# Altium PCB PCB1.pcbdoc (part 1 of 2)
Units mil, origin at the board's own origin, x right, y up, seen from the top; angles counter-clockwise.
Board outline 3200 x 1800 mil, 2 copper layers (Top Layer, Bottom Layer), stack 62.206 mil thick; 104 components, 97 nets, 542 pads, 186 vias.
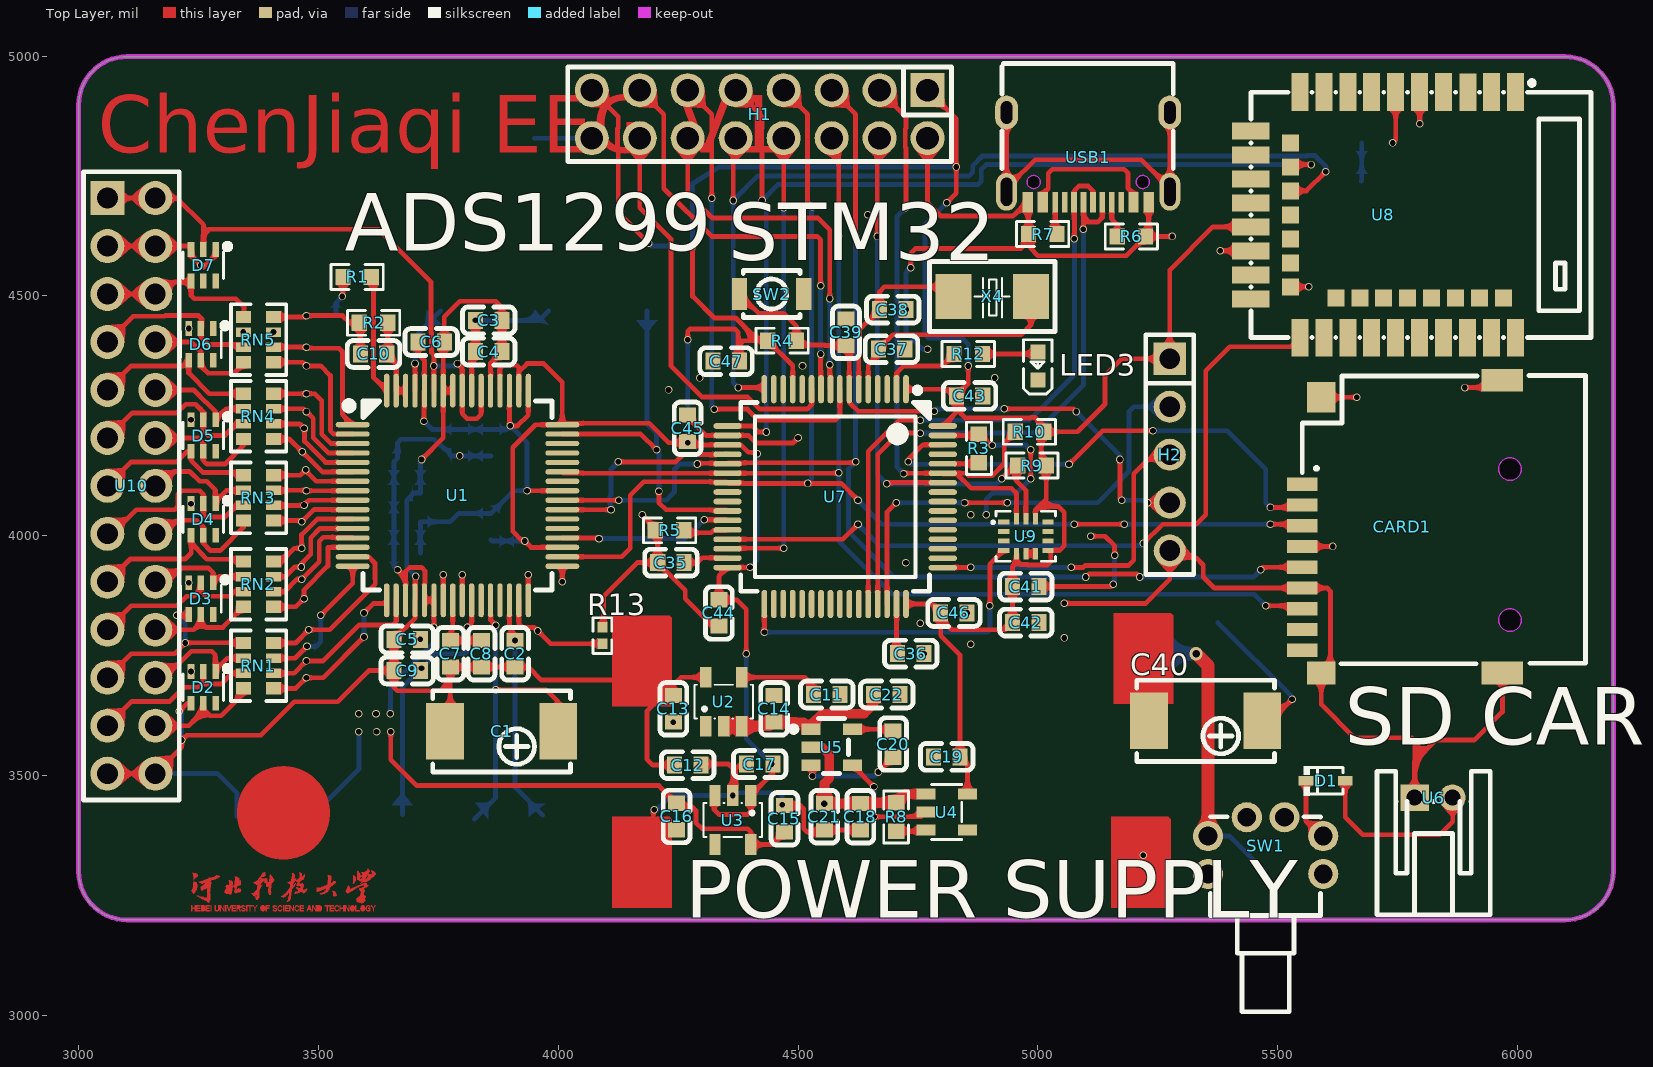
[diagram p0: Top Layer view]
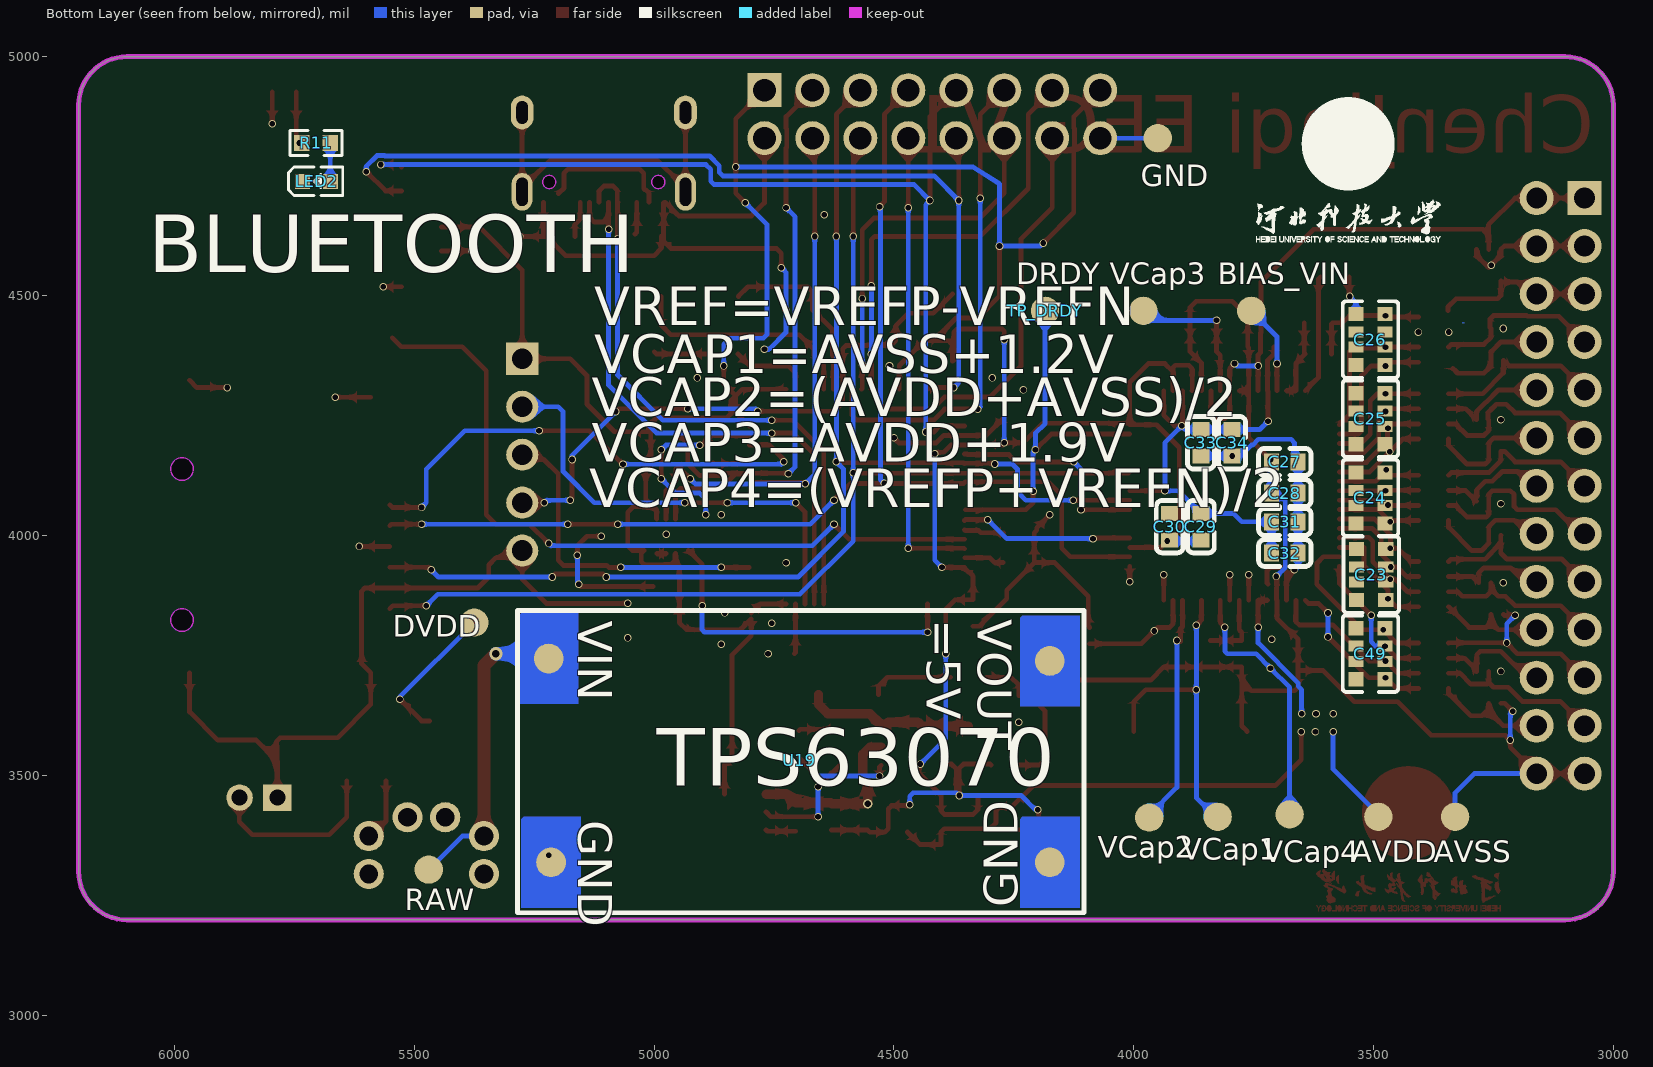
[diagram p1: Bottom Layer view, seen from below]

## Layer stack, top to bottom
Top Solder Mask Layer: solder mask 0.394, Dk 3.3
Top Layer: signal copper 1.379
Dielectric1: surface 59.449, FR4, Dk 4.5
Bottom Layer: signal copper 1.378
Bottom Solder Mask Layer: solder mask 0.394, Dk 3.3

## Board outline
3101.06,4998.82 ccw(c3101.06,4897.75) 3000,4897.75 3000,3299.88 ccw(c3101.06,3299.88) 3101.06,3198.82 6098.94,3198.82 ccw(c6098.94,3299.88) 6200,3299.88 6200,4897.75 ccw(c6098.94,4897.75) 6098.94,4998.82

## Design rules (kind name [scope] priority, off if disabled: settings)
BoardOutlineClearance copperThickness1oz [All] p0: genericclearance=10 ignorepadtopadclearanceinfootprint=FALSE except(0: Arc-SplitContinuation Track-SplitContinuation SMDPad-SplitContinuation THPad-SplitContinuation Via-SplitContinuation Fill-SplitContinuation Poly-SplitContinuation Region-SplitContinuation Text-SplitContinuation)
BoardOutlineClearance copperThickness2oz [All] p0: genericclearance=10 ignorepadtopadclearanceinfootprint=FALSE except(0: Arc-SplitContinuation Track-SplitContinuation SMDPad-SplitContinuation THPad-SplitContinuation Via-SplitContinuation Fill-SplitContinuation Poly-SplitContinuation Region-SplitContinuation Text-SplitContinuation)
BoardOutlineClearance otherClearance [All] p0: genericclearance=10 ignorepadtopadclearanceinfootprint=FALSE except(0: Arc-SplitContinuation Track-SplitContinuation SMDPad-SplitContinuation THPad-SplitContinuation Via-SplitContinuation Fill-SplitContinuation Poly-SplitContinuation Region-SplitContinuation Text-SplitContinuation)
Clearance copperThickness1oz [All] p1: gap=7 ignorepadtopadclearanceinfootprint=FALSE
Clearance copperThickness2oz [All] p1: gap=7 ignorepadtopadclearanceinfootprint=FALSE
Clearance otherClearance [All] p1: gap=7 ignorepadtopadclearanceinfootprint=FALSE
DiffPairsRouting differentialPair [All] p1: maxuncoupledlength=10 minlimit=6 maxlimit=Infinity mostfreqgap=6 toplayer_minwidth=5 toplayer_prefwidth=10 toplayer_maxwidth=100 bottomlayer_minwidth=5 bottomlayer_prefwidth=10 bottomlayer_maxwidth=100
PasteMaskExpansion pasteMaskExpansion [All] p1: expansion=0
PlaneConnect innerPlane [All] p1: planeconnectstyle=Relief reliefexpansion=20 reliefentries=4 reliefconductorwidth=10 reliefairgap=10
PolygonConnect copperRegion [All] p1: connectstyle=Relief reliefentries=4 reliefconductorwidth=10 polygonreliefangle="90 Angle" airgapwidth=10
PolygonConnect copperRegion1 [All] p1: connectstyle=Direct reliefentries=4 reliefconductorwidth=10 polygonreliefangle="90 Angle" airgapwidth=10
RoutingVias viaSize [All] p1: viastyle="Through Hole" holewidth=11.811 minholewidth=7.874 maxholewidth=27.559 width=11.811 minwidth=7.874 maxwidth=27.559
RoutingVias viaSize1 [All] p1: viastyle="Through Hole" holewidth=11.811 minholewidth=11.811 maxholewidth=11.811 width=11.811 minwidth=11.811 maxwidth=11.811
RoutingVias viaSize2 [All] p1: viastyle="Through Hole" holewidth=12.0078 minholewidth=11.811 maxholewidth=248.0314 width=12.0078 minwidth=11.811 maxwidth=248.0314
RoutingVias viaSize3 [All] p1: viastyle="Through Hole" holewidth=15.748 minholewidth=11.811 maxholewidth=248.0314 width=15.748 minwidth=11.811 maxwidth=248.0314
SolderMaskExpansion solderMaskExpansion [IsVia] p1: useseparateexpansions=TRUE expansion=-1000 expansionbottom=-1000
SolderMaskExpansion solderMaskExpansion [All] p2: useseparateexpansions=TRUE expansion=2 expansionbottom=2
Width copperThickness1oz [All] p1: maxlimit=100 minlimit=5 preferedwidth=10
Width copperThickness2oz [All] p1: maxlimit=100 minlimit=8 preferedwidth=10

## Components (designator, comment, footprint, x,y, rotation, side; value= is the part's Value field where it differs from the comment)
AVDD "" Test-Point-0.5mm 3490,3413.82 r180 bottom
AVSS "" Test-Point-0.5mm 3330,3413.82 r180 bottom
BIAS_VIN "" Test-Point-0.5mm 3755,4468.82 r180 bottom
C1 "100uF" CAP-SMD_L7.3-W4.3-RD_177EC0013 3881.89,3591.93 r0 top
C2 "100nF" C0603 3910,3753.82 r90 top
C3 "100nF" C0603 3855,4448.82 r0 top
C4 "100nF" C0603 3855,4383.82 r0 top
C5 "100nF" C0603 3685,3783.82 r180 top
C6 "100nF" C0603 3735,4403.82 r180 top
C7 "100nF" C0603 3775,3753.82 r90 top
C8 "100nF" C0603 3840,3753.82 r90 top
C9 "100nF" C0603 3685,3718.82 r0 top
C10 "100nF" C0603 3615,4378.82 r180 top
C11 "100nF" C0603 4560,3668.82 r180 top
C12 "100nF" C0603 4270.01,3521.68 r180 top
C13 "100nF" C0603 4240,3638.82 r270 top
C14 "100nF" C0603 4450,3638.82 r270 top
C15 "100nF" C0603 4471.76,3409.61 r270 top
C16 "100nF" C0603 4246.76,3414.49 r90 top
C17 "100nF" C0603 4420,3523.82 r0 top
C18 "100nF" C0603 4630,3413.82 r90 top
C19 "100nF" C0603 4810,3538.82 r0 top
C20 "100nF" C0603 4698.3,3565.47 r90 top
C21 "100nF" C0603 4555,3413.82 r90 top
C22 "100nF" C0603 4684.88,3668.82 r180 top
C23 "100nF" CAP-ARRAY-SMD_6124-8P-L1.6-W3.2-BL 3505,3918.82 r90 bottom
C24 "100nF" CAP-ARRAY-SMD_6124-8P-L1.6-W3.2-BL 3506.47,4078.82 r90 bottom
C25 "100nF" CAP-ARRAY-SMD_6124-8P-L1.6-W3.2-BL 3506.47,4243.82 r90 bottom
C26 "100nF" CAP-ARRAY-SMD_6124-8P-L1.6-W3.2-BL 3506.47,4408.82 r90 bottom
C27 "100nF" C0603 3685,4153.82 r180 bottom
C28 "100nF" C0603 3685,4088.82 r180 bottom
C29 "100nF" C0603 3860,4018.82 r270 bottom
C30 "100nF" C0603 3925,4018.82 r270 bottom
C31 "100nF" C0603 3685,4028.82 r180 bottom
C32 "100nF" C0603 3685,3963.82 r180 bottom
C33 "100nF" C0603 3860,4193.82 r270 bottom
C34 "100nF" C0603 3795,4193.82 r270 bottom
C35 "100nF" C0603 4235,3943.82 r180 top
C36 "100nF" C0603 4735,3753.82 r0 top
C37 "100nF" C0603 4695,4388.82 r0 top
C38 "100nF" C0603 4697.66,4471.4 r0 top
C39 "100nF" C0603 4600,4423.82 r90 top
C40 "100uF" CAP-SMD_L7.3-W4.3-RD_177EC0013 5350,3613.82 r0 top
C41 "100nF" C0603 4975,3893.82 r180 top
C42 "100nF" C0603 4975,3818.82 r180 top
C43 "100nF" C0603 4857.56,4291.38 r0 top
C44 "100nF" C0603 4335,3838.82 r270 top
C45 "100nF" C0603 4270,4223.82 r90 top
C46 "100nF" C0603 4825,3838.82 r0 top
C47 "100nF" C0603 4350,4363.82 r0 top
C49 "100nF" CAP-ARRAY-SMD_6124-8P-L1.6-W3.2-BL 3506.47,3753.82 r90 bottom
CARD1 "TF PUSH" TF-SMD_TF-PUSH 5760,4018.82 r90 top
D1 "B5819WS" SOD-323_L1.7-W1.3-LS2.5-FD 5600,3488.82 r180 top
D2 "TPD4E1B06DCKR" SC-70-6_L2.2-W1.3-P0.65-LS2.1-BL 3260,3683.82 r180 top
D3 "TPD4E1B06DCKR" SC-70-6_L2.2-W1.3-P0.65-LS2.1-BL 3255,3868.82 r180 top
D4 "TPD4E1B06DCKR" SC-70-6_L2.2-W1.3-P0.65-LS2.1-BL 3260,4033.82 r180 top
D5 "TPD4E1B06DCKR" SC-70-6_L2.2-W1.3-P0.65-LS2.1-BL 3260,4208.82 r180 top
D6 "TPD4E1B06DCKR" SC-70-6_L2.2-W1.3-P0.65-LS2.1-BL 3255,4398.82 r180 top
D7 "TPD4E1B06DCKR" SC-70-6_L2.2-W1.3-P0.65-LS2.1-BL 3260,4563.82 r180 top
DVDD "" Test-Point-0.5mm 5375,3818.82 r180 bottom
GND "" Test-Point-0.5mm 3950,4828.82 r180 bottom
H1 "PZ254V-12-16P" HDR-TH_16P-P2.54-V-M-R2-C8-S2.54 4420,4878.82 r180 top
H2 "PZ254V-11-05P" HDR-TH_5P-P2.54-V-M 5275,4168.82 r270 top
LED2 "LTST-C190KSKT" LED0603-RD 5703.98,4738.81 r180 bottom
LED3 "LTST-C190KSKT" LED0603-RD 5000,4353.82 r90 top
R1 "10K" R0603 3580.68,4539.5 r180 top
R2 "10K" R0603 3615,4443.82 r180 top
R3 "10K" R0603 4877.08,4181.86 r90 top
R4 "10K" R0603 4466.74,4406.52 r180 top
R5 "10K" R0603 4232.08,4011.18 r180 top
R6 "10K" R0603 5195,4623.82 r180 top
R7 "10K" R0603 5010,4628.82 r0 top
R8 "10K" R0603 4704.66,3413.48 r270 top
R9 "10K" R0603 4987.76,4146.18 r0 top
R10 "10K" R0603 4982.42,4216.52 r0 top
R11 "10K" R0603 5705,4818.82 r180 bottom
R12 "10K" R0603 4855,4378.82 r0 top
R13 "0Ω" R0402 4092.04,3791.78 r90 top
RAW "" Test-Point-0.5mm 5470,3303.82 r180 bottom
RN1 "2kΩ" RES-ARRAY-SMD_0603-8P-L3.2-W1.6-BL 3375,3728.82 r270 top
RN2 "2kΩ" RES-ARRAY-SMD_0603-8P-L3.2-W1.6-BL 3375,3898.82 r270 top
RN3 "2kΩ" RES-ARRAY-SMD_0603-8P-L3.2-W1.6-BL 3375,4078.82 r270 top
RN4 "2kΩ" RES-ARRAY-SMD_0603-8P-L3.2-W1.6-BL 3375,4248.82 r270 top
RN5 "2kΩ" RES-ARRAY-SMD_0603-8P-L3.2-W1.6-BL 3375,4408.82 r270 top
SW1 "XKB5858-Z-E" SW-TH_XKB5858-Z-E 5475,3353.82 r180 top
SW2 "B3U-1000P" KEY-SMD_B3U-1000PM 4445,4503.82 r0 top
TP_DRDY "" Test-Point-0.5mm 4185,4468.82 r90 bottom
U1 "ADS1299IPAGR" TQFP-64_L10.0-W10.0-P0.50-LS12.0-TL 3790,4083.82 r0 top
U2 "TPS72325DBVR" SOT-23-5_L3.0-W1.7-P0.95-LS2.8-BR 4345,3653.82 r270 top
U3 "TLV70025DDCR" SOT-23-5_L3.0-W1.7-P0.95-LS2.8-BR 4364.2,3407.05 r90 top
U4 "MCP1754T-3302E/OT" SOT-23-5_L2.9-W1.6-P0.95-LS2.9-BL 4810,3423.82 r270 top
U5 "TPS60401QDBVRQ1" SOT-23-5_L2.9-W1.6-P0.95-LS2.8-BR 4570,3558.82 r180 top
U6 "S2B-PH-K-S(LF)(SN)" CONN-TH_S2B-PH-K-S-LF-SN 5825,3453.82 r180 top
U7 "STM32F405RGT6" LQFP-64_L10.0-W10.0-P0.50-LS12.0-BL 4577.42,4081.52 r180 top
U8 "E73-2G4M08S1C" WIRELM-SMD_E73-2G4M08S1C 5720,4668.82 r90 top
U9 "BMI270" LGA-14_L3.0-W2.5-P0.50-BR 4975,3998.82 r180 top
U10 "DS1021-2x13SF11-B" HDR-TH_26P-P2.54-V-M-R2-C13-S2.54 3110,4103.82 r270 top
U19 "" tps63070模块 4765,3548.82 r180 bottom
USB1 "TYPE-C 16PIN 2MD(073)" USB-C-SMD_TYPE-C-16PIN-2MD-073 5105,4788.82 r180 top
VCap1 "" Test-Point-0.5mm 3825,3413.82 r90 bottom
VCap2 "" Test-Point-0.5mm 3967.72,3412.26 r90 bottom
VCap3 "" Test-Point-0.5mm 3980,4468.82 r180 bottom
VCap4 "" Test-Point-0.5mm 3675,3418.82 r90 bottom
X4 "8MHz" CRYSTAL-SMD_L5.0-W3.2 4905,4498.82 r0 top

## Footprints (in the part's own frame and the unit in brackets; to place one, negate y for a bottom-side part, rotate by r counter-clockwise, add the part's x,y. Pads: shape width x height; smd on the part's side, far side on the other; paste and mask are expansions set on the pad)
C0603 [mm]
  rect 0.8x0.9 smd: 1(-0.7,0) 2(0.7,0)
  silkscreen extent -1.39,-0.71 1.39,0.71
CAP-ARRAY-SMD_6124-8P-L1.6-W3.2-BL [mm]
  rect 0.75x0.8 smd: 1(-1.35,-0.77) 4(1.35,-0.77) 5(1.35,0.77) 8(-1.35,0.77)
  rect 0.58x0.8 smd: 2(-0.4,-0.77) 3(0.4,-0.77) 6(0.4,0.77) 7(-0.4,0.77)
  silkscreen extent -2.02,-1.47 2.02,1.47
CAP-SMD_L7.3-W4.3-RD_177EC0013 [mm]
  rect 2x3 smd paste+0 mask+0.05: 1(-3,0) 2(3,0)
  silkscreen extent -3.65,-2.15 3.65,2.15
CONN-TH_S2B-PH-K-S-LF-SN [mm]
  rect 1.5x1.4 hole 0.85: 1(1,0)
  round 1.4 hole 0.85: 2(-1,0)
  silkscreen extent -3,-1.4 3,6.2
CRYSTAL-SMD_L5.0-W3.2 [mm]
  rect 1.9x2.4 smd: 1(-2.05,0) 2(2.05,0)
  silkscreen extent -3.32,-1.85 3.33,1.85
HDR-TH_5P-P2.54-V-M [mm]
  rect 1.7x1.7 hole 1.1: 1(-5.08,0)
  round 1.7 hole 1.1: 2(-2.54,0) 3(0,0) 4(2.54,0) 5(5.08,0)
  silkscreen extent -6.35,-1.27 6.35,1.27
HDR-TH_16P-P2.54-V-M-R2-C8-S2.54 [mm]
  rect 1.8x1.8 hole 1.2: 1(-8.89,-1.27)
  round 1.8 hole 1.2: 2(-8.89,1.27) 3(-6.35,-1.27) 4(-6.35,1.27) 5(-3.81,-1.27) 6(-3.81,1.27) 7(-1.27,-1.27) 8(-1.27,1.27) 9(1.27,-1.27) 10(1.27,1.27) 11(3.81,-1.27) 12(3.81,1.27) 13(6.35,-1.27) 14(6.35,1.27) 15(8.89,-1.27) 16(8.89,1.27)
  silkscreen extent -10.16,-2.5 10.16,2.5
HDR-TH_26P-P2.54-V-M-R2-C13-S2.54 [mm]
  rect 1.8x1.8 hole 1.1: 1(-15.24,-1.27)
  round 1.8 hole 1.1: 2(-15.24,1.27) 3(-12.7,-1.27) 4(-12.7,1.27) 5(-10.16,-1.27) 6(-10.16,1.27) 7(-7.62,-1.27) 8(-7.62,1.27) 9(-5.08,-1.27) 10(-5.08,1.27) 11(-2.54,-1.27) 12(-2.54,1.27) 13(0,-1.27) 14(0,1.27) 15(2.54,-1.27) 16(2.54,1.27) 17(5.08,-1.27) 18(5.08,1.27) 19(7.62,-1.27) 20(7.62,1.27) 21(10.16,-1.27) 22(10.16,1.27) 23(12.7,-1.27) 24(12.7,1.27) 25(15.24,-1.27) 26(15.24,1.27)
  silkscreen extent -16.64,-2.54 16.64,2.54
KEY-SMD_B3U-1000PM [mm]
  rect 0.8x1.7 smd: 1(-1.7,0) 2(1.7,0)
  silkscreen extent -1.5,-1.25 1.5,1.25
LED0603-RD [mm]
  rect 0.8x0.8 smd: 1(-0.749,0) 2(0.749,0)
  silkscreen extent -1.49,-0.75 1.39,0.76
LGA-14_L3.0-W2.5-P0.50-BR [mm]
  rect 0.6x0.27 smd: 1(1.17,-0.75) 2(1.17,-0.25) 3(1.17,0.25) 4(1.17,0.75) 8(-1.17,0.75) 9(-1.17,0.25) 10(-1.17,-0.25) 11(-1.17,-0.75)
  rect 0.27x0.6 smd: 5(0.5,0.92) 6(0,0.92) 7(-0.5,0.92) 12(-0.5,-0.92) 13(0,-0.92) 14(0.5,-0.92)
  silkscreen extent -1.58,-1.33 1.8,1.33
LQFP-64_L10.0-W10.0-P0.50-LS12.0-BL [mm]
  oval 0.3x1.5 smd: 1(-3.75,-5.688) 2(-3.25,-5.688) 3(-2.75,-5.688) 4(-2.25,-5.688) 5(-1.75,-5.688) 6(-1.25,-5.688) 7(-0.75,-5.688) 8(-0.25,-5.688) 9(0.25,-5.688) 10(0.75,-5.688) 11(1.25,-5.688) 12(1.75,-5.688) 13(2.25,-5.688) 14(2.75,-5.688) 15(3.25,-5.688) 16(3.75,-5.688) 33(3.75,5.688) 34(3.25,5.688) 35(2.75,5.688) 36(2.25,5.688) 37(1.75,5.688) 38(1.25,5.688) 39(0.75,5.688) 40(0.25,5.688) 41(-0.25,5.688) 42(-0.75,5.688) 43(-1.25,5.688) 44(-1.75,5.688) 45(-2.25,5.688) 46(-2.75,5.688) 47(-3.25,5.688) 48(-3.75,5.688)
  oval 1.5x0.3 smd: 17(5.7,-3.738) 18(5.7,-3.238) 19(5.7,-2.738) 20(5.7,-2.238) 21(5.7,-1.738) 22(5.7,-1.238) 23(5.7,-0.738) 24(5.7,-0.238) 25(5.7,0.262) 26(5.7,0.762) 27(5.7,1.262) 28(5.7,1.762) 29(5.7,2.262) 30(5.7,2.762) 31(5.7,3.262) 32(5.7,3.762) 49(-5.7,3.762) 50(-5.7,3.262) 51(-5.7,2.762) 52(-5.7,2.262) 53(-5.7,1.762) 54(-5.7,1.262) 55(-5.7,0.762) 56(-5.7,0.262) 57(-5.7,-0.238) 58(-5.7,-0.738) 59(-5.7,-1.238) 60(-5.7,-1.738) 61(-5.7,-2.238) 62(-5.7,-2.738) 63(-5.7,-3.238) 64(-5.7,-3.738)
  silkscreen extent -5,-5.78 5,5.01
R0402 [mm]
  rect 0.566x0.54 smd paste-100 mask+0.051: 1(-0.433,0) 2(0.433,0)
  silkscreen extent -0.94,-0.5 0.94,0.5
R0603 [mil]
  rect 31.75x34.02 smd paste-3937.01 mask+2: 1(-29.66,0) 2(29.66,0)
  silkscreen extent -55,-26 55,26
RES-ARRAY-SMD_0603-8P-L3.2-W1.6-BL [mm]
  rect 0.65x0.8 smd: 1(-1.2,-0.8) 4(1.2,-0.8) 5(1.2,0.8) 8(-1.2,0.8)
  rect 0.5x0.8 smd: 2(-0.4,-0.8) 3(0.4,-0.8) 6(0.4,0.8) 7(-0.4,0.8)
  silkscreen extent -1.87,-1.45 1.87,1.47
SC-70-6_L2.2-W1.3-P0.65-LS2.1-BL [mm]
  rect 0.35x0.78 smd: 1(-0.65,-0.84) 2(0,-0.84) 3(0.65,-0.84) 4(0.65,0.84) 5(0,0.84) 6(-0.65,0.84)
  silkscreen extent -1.43,-1.14 1.08,0.7
SOD-323_L1.7-W1.3-LS2.5-FD [mm]
  rect 0.78x0.5 smd: 1(-1.04,0) 2(1.04,0)
  silkscreen extent -0.93,-0.78 1.15,0.78
SOT-23-5_L2.9-W1.6-P0.95-LS2.8-BR [mm]
  rect 1x0.6 smd paste+0 mask+0.05: 1(1.1,-0.95) 2(1.1,0) 3(1.1,0.95) 4(-1.1,0.95) 5(-1.1,-0.95)
  silkscreen extent -0.89,-1.52 2.16,1.4
SOT-23-5_L2.9-W1.6-P0.95-LS2.9-BL [mm]
  rect 0.6x1 smd paste+0 mask+0.05: 1(-0.95,-1.1) 2(0,-1.1) 3(0.95,-1.1) 4(0.95,1.1) 5(-0.95,1.1)
  silkscreen extent -1.45,-0.8 1.45,0.8
SOT-23-5_L3.0-W1.7-P0.95-LS2.8-BR [mm]
  rect 1.1x0.6 smd: 1(1.3,-0.95) 2(1.3,0) 3(1.3,0.95) 4(-1.3,0.95) 5(-1.3,-0.95)
  silkscreen extent -0.9,-1.55 0.9,1.55
SW-TH_XKB5858-Z-E [mm]
  round 1.6 hole 1: 1(-3.05,1.5) 2(-3.05,-0.5) 3(3.05,1.5) 4(3.05,-0.5) 5(-1,-1.5) 6(1,-1.5)
  silkscreen extent -2.9,-1.52 2.92,8.8
Test-Point-0.5mm [mm]
  round 1.5 smd: 1(0,0)
TF-SMD_TF-PUSH [mm]
  rect 0.7x1.6 smd: 1(2.25,5.3) 2(1.15,5.3) 3(0.05,5.3) 4(-1.05,5.3) 5(-2.15,5.3) 6(-3.25,5.3) 7(-4.35,5.3) 8(-5.45,5.3) CD(-6.55,5.3)
  rect 1.2x1.5 smd: 10(-7.75,4.3)
  rect 1.2x2.2 smd: 11(-7.75,-5.3) 12(7.75,-5.3)
  rect 1.6x1.5 smd: 13(6.85,4.3)
  Board Outline Layer circle w0.003: c-4.95,-5.7 r0.6
  Board Outline Layer circle w0.003: c3.05,-5.7 r0.6
  Board Outline Layer region: -4.95,-6.3 -5.21,-6.241 -5.419,-6.074 -5.535,-5.834 -5.535,-5.567 -5.419,-5.326 -5.21,-5.159 -4.95,-5.1 -4.95,-5.1 -4.69,-5.159 -4.481,-5.326 -4.365,-5.567 -4.365,-5.834 -4.481,-6.074 -4.69,-6.241 -4.95,-6.3
  Board Outline Layer region: -4.95,-6.3 -5.054,-6.291 -5.155,-6.264 -5.25,-6.22 -5.336,-6.16 -5.41,-6.086 -5.47,-6 -5.514,-5.905 -5.541,-5.804 -5.55,-5.7 -5.541,-5.596 -5.514,-5.495 -5.47,-5.4 -5.41,-5.314 -5.336,-5.24 -5.25,-5.18 -5.155,-5.136 -5.054,-5.109 -4.95,-5.1 -4.846,-5.109 -4.745,-5.136 -4.65,-5.18 -4.564,-5.24 -4.49,-5.314 -4.43,-5.4 -4.386,-5.495 -4.359,-5.596 -4.35,-5.7 -4.359,-5.804 -4.386,-5.905 -4.43,-6 -4.49,-6.086 -4.564,-6.16 -4.65,-6.22 -4.745,-6.264 -4.846,-6.291
  Board Outline Layer region: 3.05,-6.3 2.79,-6.241 2.581,-6.074 2.465,-5.834 2.465,-5.567 2.581,-5.326 2.79,-5.159 3.05,-5.1 3.05,-5.1 3.31,-5.159 3.519,-5.326 3.635,-5.567 3.635,-5.834 3.519,-6.074 3.31,-6.241 3.05,-6.3
  Board Outline Layer region: 3.05,-6.3 2.946,-6.291 2.845,-6.264 2.75,-6.22 2.664,-6.16 2.59,-6.086 2.53,-6 2.486,-5.905 2.459,-5.804 2.45,-5.7 2.459,-5.596 2.486,-5.495 2.53,-5.4 2.59,-5.314 2.664,-5.24 2.75,-5.18 2.845,-5.136 2.946,-5.109 3.05,-5.1 3.154,-5.109 3.255,-5.136 3.35,-5.18 3.436,-5.24 3.51,-5.314 3.57,-5.4 3.614,-5.495 3.641,-5.596 3.65,-5.7 3.641,-5.804 3.614,-5.905 3.57,-6 3.51,-6.086 3.436,-6.16 3.35,-6.22 3.255,-6.264 3.154,-6.291
  Multi-Layer board cut-out: -4.95,-6.3 -5.21,-6.241 -5.419,-6.074 -5.535,-5.834 -5.535,-5.567 -5.419,-5.326 -5.21,-5.159 -4.95,-5.1 -4.95,-5.1 -4.69,-5.159 -4.481,-5.326 -4.365,-5.567 -4.365,-5.834 -4.481,-6.074 -4.69,-6.241 -4.95,-6.3
  Multi-Layer board cut-out: 3.05,-6.3 2.79,-6.241 2.581,-6.074 2.465,-5.834 2.465,-5.567 2.581,-5.326 2.79,-5.159 3.05,-5.1 3.05,-5.1 3.31,-5.159 3.519,-5.326 3.635,-5.567 3.635,-5.834 3.519,-6.074 3.31,-6.241 3.05,-6.3
  silkscreen extent -7.26,-9.7 8,5.3
tps63070模块 [mm]
  round 1.571 smd: 1(-11.556,4.952) 2(-11.429,-5.843) 3(14.987,4.825) 4(14.987,-5.843)
  Top Layer region: -13.015,7.357 -9.985,7.357 -9.985,2.549 -13.129,2.549 -13.129,7.243
  Top Layer region: -12.888,-3.438 -9.858,-3.438 -9.858,-8.246 -13.002,-8.246 -13.002,-3.552
  Top Layer region: 13.528,7.23 16.558,7.23 16.558,2.422 13.414,2.422 13.414,7.116
  Top Layer region: 13.528,-3.438 16.558,-3.438 16.558,-8.246 13.414,-8.246 13.414,-3.552
  Bottom Layer region: -13.015,7.357 -9.985,7.357 -9.985,2.549 -13.129,2.549 -13.129,7.243
  Bottom Layer region: -12.888,-3.438 -9.858,-3.438 -9.858,-8.246 -13.002,-8.246 -13.002,-3.552
  Bottom Layer region: 13.528,7.23 16.558,7.23 16.558,2.422 13.414,2.422 13.414,7.116
  Bottom Layer region: 13.528,-3.438 16.558,-3.438 16.558,-8.246 13.414,-8.246 13.414,-3.552
  Multi-Layer region: -13.015,7.357 -9.985,7.357 -9.985,2.549 -13.129,2.549 -13.129,7.243
  Multi-Layer region: -12.888,-3.438 -9.858,-3.438 -9.858,-8.246 -13.002,-8.246 -13.002,-3.552
  Multi-Layer region: 13.528,7.23 16.558,7.23 16.558,2.422 13.414,2.422 13.414,7.116
  Multi-Layer region: 13.528,-3.438 16.558,-3.438 16.558,-8.246 13.414,-8.246 13.414,-3.552
  silkscreen extent -13.21,-8.51 16.79,7.49
TQFP-64_L10.0-W10.0-P0.50-LS12.0-TL [mm]
  oval 1.8x0.28 smd paste-100 mask+0.051: 1(-5.55,3.75) 2(-5.55,3.25) 3(-5.55,2.75) 4(-5.55,2.25) 5(-5.55,1.75) 6(-5.55,1.25) 7(-5.55,0.75) 8(-5.55,0.25) 9(-5.55,-0.25) 10(-5.55,-0.75) 11(-5.55,-1.25) 12(-5.55,-1.75) 13(-5.55,-2.25) 14(-5.55,-2.75) 15(-5.55,-3.25) 16(-5.55,-3.75) 33(5.55,-3.75) 34(5.55,-3.25) 35(5.55,-2.75) 36(5.55,-2.25) 37(5.55,-1.75) 38(5.55,-1.25) 39(5.55,-0.75) 40(5.55,-0.25) 41(5.55,0.25) 42(5.55,0.75) 43(5.55,1.25) 44(5.55,1.75) 45(5.55,2.25) 46(5.55,2.75) 47(5.55,3.25) 48(5.55,3.75)
  oval 0.28x1.8 smd paste-100 mask+0.051: 17(-3.75,-5.55) 18(-3.25,-5.55) 19(-2.75,-5.55) 20(-2.25,-5.55) 21(-1.75,-5.55) 22(-1.25,-5.55) 23(-0.75,-5.55) 24(-0.25,-5.55) 25(0.25,-5.55) 26(0.75,-5.55) 27(1.25,-5.55) 28(1.75,-5.55) 29(2.25,-5.55) 30(2.75,-5.55) 31(3.25,-5.55) 32(3.75,-5.55) 49(3.75,5.55) 50(3.25,5.55) 51(2.75,5.55) 52(2.25,5.55) 53(1.75,5.55) 54(1.25,5.55) 55(0.75,5.55) 56(0.25,5.55) 57(-0.25,5.55) 58(-0.75,5.55) 59(-1.25,5.55) 60(-1.75,5.55) 61(-2.25,5.55) 62(-2.75,5.55) 63(-3.25,5.55) 64(-3.75,5.55)
  silkscreen extent -5.95,-5 5,5
USB-C-SMD_TYPE-C-16PIN-2MD-073 [mm]
  oval 1.2x1.8 hole 0.6 slot 1.2 at 90 deg paste+0 mask+0.05: 13(-4.325,-2.375) 14(4.325,-2.375)
  oval 1.1x2 hole 0.6 slot 1.5 at 90 deg paste+0 mask+0.05: 13(-4.325,1.825) 14(4.325,1.825)
  rect 0.55x1.1 smd paste+0 mask+0.05: A1B12(-3.2,2.375) A4B9(-2.4,2.375) B1A12(3.2,2.375) B4A9(2.4,2.375)
  rect 0.3x1.1 smd paste+0 mask+0.05: A5(-1.25,2.375) A6(-0.25,2.375) A7(0.25,2.375) A8(1.25,2.375) B5(1.75,2.375) B6(0.75,2.375) B7(-0.75,2.375) B8(-1.75,2.375)
  Board Outline Layer circle w0.003: c-2.89,1.305 r0.35
  Board Outline Layer circle w0.003: c2.89,1.305 r0.35
  Board Outline Layer region: -3.24,1.305 -3.205,1.457 -3.108,1.579 -2.968,1.646 -2.812,1.646 -2.672,1.579 -2.575,1.457 -2.54,1.305 -2.54,1.305 -2.575,1.153 -2.672,1.031 -2.812,0.964 -2.968,0.964 -3.108,1.031 -3.205,1.153 -3.24,1.305
  Board Outline Layer region: -3.24,1.305 -3.231,1.383 -3.205,1.457 -3.164,1.523 -3.108,1.579 -3.042,1.62 -2.968,1.646 -2.89,1.655 -2.812,1.646 -2.738,1.62 -2.672,1.579 -2.616,1.523 -2.575,1.457 -2.549,1.383 -2.54,1.305 -2.549,1.227 -2.575,1.153 -2.616,1.087 -2.672,1.031 -2.738,0.99 -2.812,0.964 -2.89,0.955 -2.968,0.964 -3.042,0.99 -3.108,1.031 -3.164,1.087 -3.205,1.153 -3.231,1.227
  Board Outline Layer region: 2.54,1.305 2.575,1.457 2.672,1.579 2.812,1.646 2.968,1.646 3.108,1.579 3.205,1.457 3.24,1.305 3.24,1.305 3.205,1.153 3.108,1.031 2.968,0.964 2.812,0.964 2.672,1.031 2.575,1.153 2.54,1.305
  Board Outline Layer region: 2.54,1.305 2.549,1.383 2.575,1.457 2.616,1.523 2.672,1.579 2.738,1.62 2.812,1.646 2.89,1.655 2.968,1.646 3.042,1.62 3.108,1.579 3.164,1.523 3.205,1.457 3.231,1.383 3.24,1.305 3.231,1.227 3.205,1.153 3.164,1.087 3.108,1.031 3.042,0.99 2.968,0.964 2.89,0.955 2.812,0.964 2.738,0.99 2.672,1.031 2.616,1.087 2.575,1.153 2.549,1.227
  Multi-Layer board cut-out: -3.24,1.305 -3.205,1.457 -3.108,1.579 -2.968,1.646 -2.812,1.646 -2.672,1.579 -2.575,1.457 -2.54,1.305 -2.54,1.305 -2.575,1.153 -2.672,1.031 -2.812,0.964 -2.968,0.964 -3.108,1.031 -3.205,1.153 -3.24,1.305
  Multi-Layer board cut-out: 2.54,1.305 2.575,1.457 2.672,1.579 2.812,1.646 2.968,1.646 3.108,1.579 3.205,1.457 3.24,1.305 3.24,1.305 3.205,1.153 3.108,1.031 2.968,0.964 2.812,0.964 2.672,1.031 2.575,1.153 2.54,1.305
  silkscreen extent -4.5,-4.97 4.57,0.6
WIRELM-SMD_E73-2G4M08S1C [mm]
  rect 2x0.9 smd paste+0 mask+0.05: 1(6.505,-7.015) 2(6.505,-5.745) 3(6.5,-4.5) 4(6.505,-3.205) 5(6.505,-1.935) 6(6.505,-0.665) 7(6.505,0.605) 8(6.505,1.875) 9(6.505,3.145) 10(6.505,4.415) 26(-6.505,4.415) 27(-6.505,3.145) 29(-6.505,1.875) 31(-6.505,0.605) 33(-6.505,-0.665) 35(-6.505,-1.935) 37(-6.505,-3.205) 39(-6.505,-4.475) 41(-6.505,-5.745) 43(-6.505,-7.015)
  rect 0.9x2 smd paste+0 mask+0.05: 11(4.445,7.015) 13(3.175,7.015) 15(1.905,7.015) 17(0.635,7.015) 19(-0.635,7.015) 21(-1.905,7.015) 23(-3.175,7.015) 25(-4.445,7.015)
  rect 0.9x0.9 smd paste+0 mask+0.05: 12(3.81,4.915) 14(2.54,4.915) 16(1.27,4.915) 18(0,4.915) 20(-1.27,4.915) 22(-2.54,4.915) 24(-3.81,4.915) 28(-4.405,2.51) 30(-4.405,1.24) 32(-4.405,-0.03) 34(-4.405,-1.3) 36(-4.405,-2.57) 38(-4.405,-3.84) 40(-4.405,-5.11) 42(-4.405,-6.38)
  silkscreen extent -6.5,-11 7.11,7

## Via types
v1: diameter 15.75, hole 11.8, Top Layer to Bottom Layer, 184 vias
v2: diameter 19.68, hole 13.8, Top Layer to Bottom Layer, 1 vias
v3: diameter 27.56, hole 15.7, Top Layer to Bottom Layer, 1 vias

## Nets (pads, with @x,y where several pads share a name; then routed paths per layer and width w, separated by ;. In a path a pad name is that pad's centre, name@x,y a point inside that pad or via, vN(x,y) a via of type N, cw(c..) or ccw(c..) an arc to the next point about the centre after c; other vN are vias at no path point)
1N: D3.4 RN1.1 U10.21 | length 404
  Top Layer w10: U10.21@3060,3703.82 3110,3753.82 3200,3753.82 v1(3222.5,3776.32) 3227.06,3776.32 3227.55,3776.81 3342.75,3776.81 RN1.1@3343.5,3776.06 ; v1(3205,3833.82) 3227.48,3833.82 D3.4@3229.41,3835.75
  Bottom Layer w10: v1(3205,3833.82) 3222.5,3816.32 v1(3222.5,3776.32)
1P: D2.1 RN1.2 U10.22 | length 257.1
  Top Layer w10: U10.22@3160,3703.82 3180,3703.82 3235,3758.82 3277.93,3758.82 3285,3751.74 3285,3717.48 D2.1@3285.59,3716.89 3285.59,3720.16 3310,3744.57 RN1.2@3343.5,3744.57
2N: D3.2 RN2.3 U10.19 | length 344.8
  Top Layer w10: U10.19@3060,3803.82 3110,3853.82 3205,3853.82 3225,3873.82 3240,3873.82 D3.2@3255,3888.82 ; D3.2@3255,3901.89 D3.2@3255,3888.82 ; RN2.3@3343.5,3883.07 3324.25,3883.07 3315,3873.82 3265,3873.82 3255,3883.82 D3.2@3255,3888.82
2P: D3.5 RN2.4 U10.20 | length 228.5
  Top Layer w10: U10.20@3160,3803.82 3240,3803.82 3255,3818.82 ; D3.5@3255,3835.75 3255,3818.82 ; RN2.4@3343.5,3851.58 3300.74,3808.82 3265,3808.82 3255,3818.82
3N: D4.4 RN2.1 U10.17 | length 361
  Top Layer w10: U10.17@3060,3903.82 3107.5,3951.31 3222.5,3951.31 3235,3963.82 3235,3973.82 ; D4.4@3234.41,4000.75 3235,4000.16 3235,3973.82 ; RN2.1@3343.5,3946.06 3338.74,3950.82 3267.55,3950.82 3239.78,3978.59 3235,3973.82
3P: D3.1 RN2.2 U10.18 | length 225.5
  Top Layer w10: U10.18@3160,3903.82 3185.5,3903.82 3214.51,3932.83 3270,3932.83 3280.59,3922.24 D3.1@3280.59,3901.89 3293.27,3914.57 RN2.2@3343.5,3914.57
4N: D4.2 RN3.3 U10.15 | length 393.3
  Top Layer w10: U10.15@3060,4003.82 3070,4003.82 3120,4053.82 3200,4053.82 3207.07,4060.89 3207.07,4085.89 3214.94,4093.75 3252.93,4093.75 3260,4086.68 D4.2@3260,4066.89 3260,4043.82 3265,4038.82 3305,4038.82 3329.25,4063.07 RN3.3@3343.5,4063.07
4P: D4.5 RN3.4 U10.16 | length 276
  Top Layer w10: U10.16@3160,4003.82 3178.56,4003.82 3206.83,4032.08 3246.29,4032.08 3260,4018.37 D4.5@3260,4000.75 3260,3983.82 3275,3968.82 3295,3968.82 3343.5,4017.32 RN3.4@3343.5,4031.58
5N: D5.4 RN3.1 U10.13 | length 345.1
  Top Layer w10: U10.13@3060,4103.82 3110,4153.82 3205,4153.82 3226.93,4175.75 D5.4@3234.41,4175.75 3235,4175.16 3235,4156.03 3259.62,4131.42 3338.14,4131.42 RN3.1@3343.5,4126.06
5P: D4.1 RN3.2 U10.14 | length 241.8
  Top Layer w10: U10.14@3160,4103.82 3170,4103.82 3200,4133.82 3231.77,4133.82 3252.17,4113.42 3267.02,4113.42 3285,4095.44 3285,4081.3 D4.1@3290,4076.3 ; D4.1@3285.59,4071.89 D4.1@3290,4076.3 ; RN3.2@3343.5,4094.57 3342.93,4094 3307.7,4094 D4.1@3290,4076.3
6N: D5.2 RN4.3 U10.11 | length 373.9
  Top Layer w10: U10.11@3060,4203.82 3112.07,4255.89 3205,4255.89 3223.19,4274.08 3243.85,4274.08 3261.63,4256.3 3261.63,4243.51 D5.2@3260,4241.89 3260,4218.82 3270,4208.82 3305,4208.82 3329.25,4233.07 RN4.3@3343.5,4233.07
6P: D5.5 RN4.4 U10.12 | length 257.6
  Top Layer w10: U10.12@3160,4203.82 3249.56,4203.82 3260,4193.37 D5.5@3260,4175.75 3260,4156.48 3267.07,4149.41 3305.59,4149.41 3343.5,4187.32 RN4.4@3343.5,4201.58
7N: D6.4 RN4.1 U10.9 | length 353.5
  Top Layer w10: U10.9@3060,4303.82 3110,4353.82 3217.48,4353.82 D6.4@3229.41,4365.75 3229.41,4339.41 3272.76,4296.06 RN4.1@3343.5,4296.06
7P: D5.1 RN4.2 U10.10 | length 228.1
  Top Layer w10: U10.10@3160,4303.82 3239.56,4303.82 3265.31,4278.06 3265.75,4278.06 3285.59,4258.23 D5.1@3285.59,4241.89 3308.27,4264.57 RN4.2@3343.5,4264.57
8N: D6.2 RN5.3 U10.7 | length 358.7
  Top Layer w10: U10.7@3060,4403.82 3113.58,4457.4 3179.23,4457.4 3180.64,4458.82 3250,4458.82 3257.07,4451.74 3257.07,4433.96 D6.2@3255,4431.89 3255,4413.82 3270,4398.82 3337.75,4398.82 RN5.3@3343.5,4393.07
8P: D6.5 RN5.4 U10.8 | length 223.8
  Top Layer w10: U10.8@3160,4403.82 3235,4403.82 3255,4383.82 D6.5@3255,4365.75 3255,4353.56 3269.15,4339.41 3269.41,4339.41 3270,4338.82 3325,4338.82 RN5.4@3335,4348.82
$1N14: C2.2 U1.30 VCap2.1 | length 476.3
  Top Layer w10: U1.30@3898.27,3865.32 3898.27,3810.55 3902.44,3806.38 C2.2@3902.44,3778.82
  Bottom Layer w10: v1(3910,3781.38) 3910,3474.97 VCap2.1@3967.72,3417.26
$1N16: C3.1 C4.1 U1.55 VCap3.1 | length 310.6
  Top Layer w10: U1.55@3819.53,4302.32 3819.53,4375.91 C4.1@3827.44,4383.82 v1(3827.44,4448.82)
  Bottom Layer w10: v1(3827.44,4448.82) 3960,4448.82 VCap3.1@3980,4468.82
$1N23: C7.2 C8.2 U1.24 | length 151.1
  Top Layer w10: U1.24@3780.16,3865.32 3780,3865.16 3780,3803.82 3775,3798.82 C7.2@3775,3781.38 C8.2@3840,3781.38
$1N26: C9.2 U1.26 VCap4.1 | length 541.5
  Top Layer w10: v1(3810,3808.82) 3819.53,3818.35 U1.26@3819.53,3865.32
  Bottom Layer w10: VCap4.1@3675,3418.82 3675,3683.82 v1(3715,3723.82) 3745,3753.82 3805,3753.82 3810,3758.82 v1(3810,3808.82)
$1N27: C1.2 U1.28 VCap1.1 | length 682.1
  Top Layer w10: U1.28@3858.9,3865.32 3858.9,3823.82 v1(3869.45,3813.27) ; v1(3869.45,3678.82) 3975,3678.82 4000,3653.82 C1.2@4000,3591.93
  Bottom Layer w10: VCap1.1@3825,3408.82 3869.45,3453.27 v1(3869.45,3678.82) v1(3869.45,3813.27)
$1N32: R1.1 U1.64 | length 250.4
  Top Layer w10: R1.1@3610.34,4539.5 3615,4534.84 3615,4329.68 U1.64@3642.36,4302.32
$1N49: C10.1 R2.1 U1.62 U1.63 | length 170.1
  Top Layer w10: R2.1@3644.66,4443.82 3644.66,4380.92 C10.1@3642.56,4378.82 3662.05,4359.33 U1.63@3662.05,4302.32 U1.62@3681.73,4302.32
$1N53: BIAS_VIN.1 U1.61 | length 188.7
  Top Layer w10: U1.61@3701.42,4302.32 v1(3701.42,4358.82)
  Bottom Layer w10: v1(3701.42,4358.82) 3701.42,4415.24 BIAS_VIN.1@3755,4468.82
$1N56: C11.2 U2.4 | length 175.3
  Top Layer w10: U2.4@4382.4,3705 4513.81,3705 4532.44,3686.38 C11.2@4532.44,3668.82
$1N71: C20.1 U5.3 | length 208.5
  Top Layer w10: U5.3@4526.69,3521.42 4530,3518.11 v1(4530,3498.82) ; v1(4667.64,3507.25) C20.1@4698.3,3537.91
  Bottom Layer w10: v1(4530,3498.82) 4659.21,3498.82 v1(4667.64,3507.25)
$1N72: C20.2 U5.5 | length 86.3
  Top Layer w10: U5.5@4613.31,3596.22 4695.11,3596.22 C20.2@4698.3,3593.03
$1N80: D1.1 U6.2 | length 376.8
  Top Layer w10: D1.1@5640.94,3488.82 5640.94,3412.88 5677.5,3376.32 5837.5,3376.32 5865,3403.82 5865,3453.19 U6.2@5864.37,3453.82
$1N89: D1.2 SW1.2 | length 133
  Top Layer w10: D1.2@5559.06,3488.82 5559.06,3404.76 5590.31,3373.5 SW1.2@5595.08,3373.5
$1N212: C35.1 U7.31 | length 83.9
  Top Layer w10: C35.1@4272.56,3943.82 4290,3943.82 4300,3953.82 U7.31@4352.3,3953.82
$1N213: C36.1 U7.47 | length 104.6
  Top Layer w10: U7.47@4705.37,3857.57 4705.37,3755.88 C36.1@4707.44,3753.82
$1N218: C37.1 U7.5 X4.2 | length 490.7
  Top Layer w10: U7.5@4646.32,4305.46 4646.32,4355.14 4667.44,4376.26 C37.1@4667.44,4388.82 4697.44,4418.82 4965,4418.82 4985.71,4439.53 X4.2@4985.71,4498.82
$1N219: C38.1 U7.6 X4.1 | length 388
  Top Layer w10: U7.6@4626.63,4305.46 4626.63,4373.89 4628.7,4375.96 4628.7,4429.99 C38.1@4670.1,4471.4 4670.1,4508.92 4680,4518.82 4804.29,4518.82 X4.1@4824.29,4498.82
$1N221: R3.1 U7.60 | length 76.2
  Top Layer w10: U7.60@4801.83,4149.95 4874.84,4149.95 R3.1@4877.08,4152.2
$1N229: R5.1 U7.28 | length 83.7
  Top Layer w10: R5.1@4271.74,4006.18 4319.21,4006.18 4323.5,4010.46 4351.33,4010.46 U7.28@4353.01,4012.15
$1N265: R6.2 USB1.A5 | length 76.1
  Top Layer w10: USB1.A5@5154.21,4695.31 5154.2,4659.61 5165.34,4648.48 R6.2@5165.34,4623.82
$1N267: R7.2 USB1.B5 | length 68
  Top Layer w10: USB1.B5@5036.1,4695.31 5036.1,4632.38 R7.2@5039.66,4628.82
$1N273: R12.1 U7.2 | length 170.1
  Top Layer w10: U7.2@4705.37,4305.46 4705.37,4339.19 4720,4353.82 4800.34,4353.82 R12.1@4825.34,4378.82
$1N342: R11.1 U8.6 | length 114
  Top Layer w10: v1(5740,4818.82) 5746.18,4825 U8.6@5746.18,4924.92
  Bottom Layer w10: R11.1@5734.66,4818.82 v1(5740,4818.82)
$1N343: LED2.2 R11.2 | length 80.4
  Bottom Layer w10: LED2.2@5674.49,4738.81 5675.34,4739.66 R11.2@5675.34,4818.82
$1N346: LED3.2 R12.2 | length 117.2
  Top Layer w10: R12.2@4884.66,4378.82 4995.51,4378.82 LED3.2@4999.99,4383.3
$1N350: R8.2 U4.3 | length 63.1
  Top Layer w10: R8.2@4704.66,3383.82 4764.09,3383.82 U4.3@4766.69,3386.42
+5V: C18.2 C21.2 R8.1 U4.1 U5.2 U19.3 | length 371
  Top Layer w19.68: U5.2@4526.69,3558.82 4549.99,3558.82 4565,3543.82 4565,3493.82 4555,3483.82 v2(4555,3441.38) C18.2@4630,3441.38 4631.76,3443.14 R8.1@4704.66,3443.14 4722.74,3461.21 U4.1@4766.69,3461.21
-5V: C14.2 C22.2 U2.2 U2.3 U5.1 | length 369.5
  Top Layer w19.68: U2.2@4345,3602.63 U2.3@4382.4,3602.63 4441.38,3602.63 C14.2@4450,3611.26 4511.65,3611.26 U5.1@4526.69,3596.21 4526.69,3605.51 4550,3628.82 4637.64,3628.82 4657.32,3648.5 C22.2@4657.32,3668.82
_SBR1: C49.1 RN1.5 U1.17 | length 341.3
  Top Layer w10: RN1.5@3406.5,3681.58 3452.76,3681.58 v1(3475,3703.82) 3510,3703.82 v1(3595,3788.82) ; v1(3595,3838.82) 3615,3858.82 3635.86,3858.82 U1.17@3642.36,3865.32
  Bottom Layer w10: v1(3595,3788.82) v1(3595,3838.82)
_SBR2: C49.2 RN1.6 U1.18 | length 344.7
  Top Layer w10: RN1.6@3406.5,3713.07 3449.25,3713.07 v1(3475,3738.82) 3510,3738.82 3585,3813.82 3655,3813.82 3662.05,3820.87 U1.18@3662.05,3865.32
